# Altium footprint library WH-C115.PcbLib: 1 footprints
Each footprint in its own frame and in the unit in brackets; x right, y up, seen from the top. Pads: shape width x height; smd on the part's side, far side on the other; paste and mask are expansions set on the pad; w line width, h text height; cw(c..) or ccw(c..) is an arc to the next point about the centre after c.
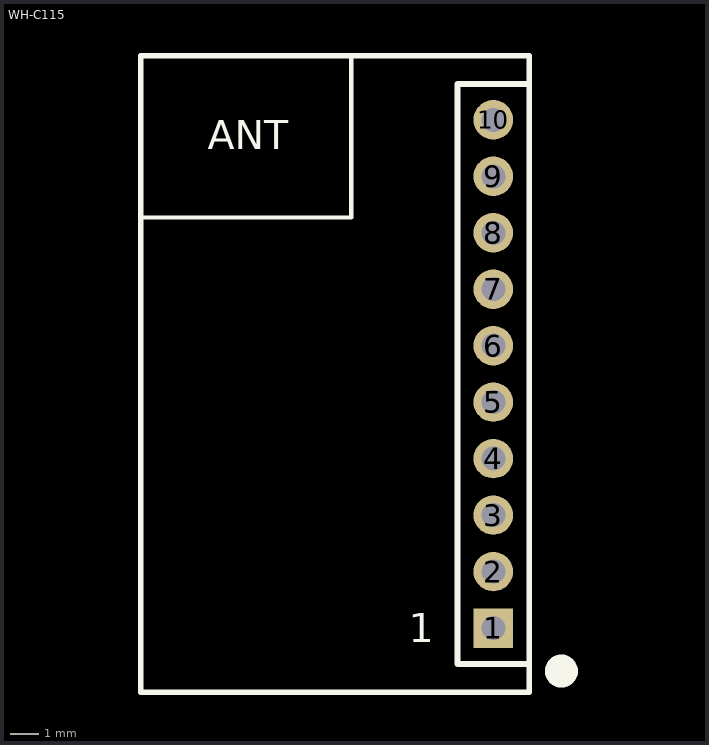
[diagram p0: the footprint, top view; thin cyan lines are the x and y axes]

## WH-C115 [mil]
pads (10):
  rect 55x55 hole 33.47: 1(-15775,-32175)
  round 55 hole 33.47: 2(-15775,-32096.26) 3(-15775,-32017.52) 4(-15775,-31938.78) 5(-15775,-31860.04) 6(-15775,-31781.3) 7(-15775,-31702.56) 8(-15775,-31623.82) 9(-15775,-31545.08) 10(-15775,-31466.34)
Top Overlay:
  circle w30: c-15680,-32235 r8
  lines w6: -16266.37,-31602.5 -15973,-31602.5 -15973,-31415 -15973,-31380.13
  lines w8: -15825,-31416.5 -15825,-32225 -15725,-32225 ; -15825,-31416.3 -15725,-31416.3 ; -15726.12,-31377.13 -15825,-31377.13 -16266.37,-31377.13 -16266.37,-31415 -16266.37,-32223.5 -16266.37,-32264.37 -15825,-32264.37 -15725.63,-32264.37 ; -15725,-32264.37 -15725,-32225 ; -15725,-31377.13 -15725,-31416.5 -15725,-32225
  text "ANT" at -16173,-31507.5 h40
  text "1" at -15893,-32195 h40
